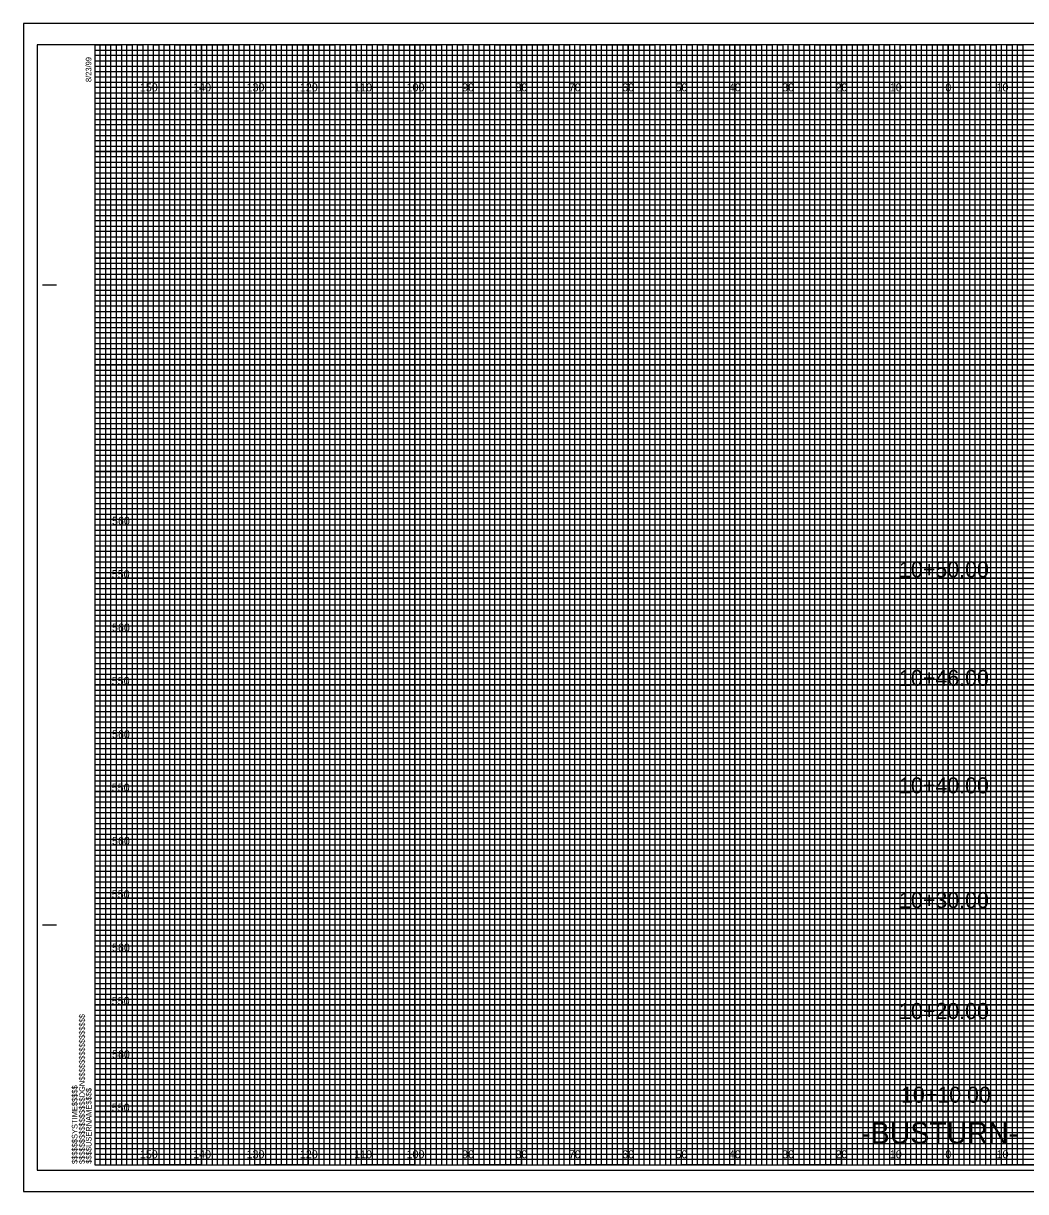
# Model space of a CAD drawing. Extents: x -13 to 323, y -5 to 214.
# Drawn here: x -13.4 to 174.5, y -5 to 214 of the extents above; entities that cross this region are included whole.
import ezdxf

# ---------------------------------------------------------------- set-up
doc = ezdxf.new("R2010")
doc.units = 0
for name, color, linetype in [('Exist Cross Section Cell', 7, 'Continuous'), ('Exist XS Center Line Elevation Label', 7, 'Continuous'), ('Exist XS Ground Line', 7, 'Continuous'), ('Prop XS Alignment Label', 7, 'Continuous'), ('Prop XS DDE Elevations', 7, 'Continuous'), ('Prop XS Ditch Slope Text', 7, 'Continuous'), ('Prop XS Ditch Standard Text', 7, 'Continuous'), ('Prop XS EOT Tick Mark', 7, 'Continuous'), ('Prop XS Finish Grade', 7, 'Continuous'), ('Prop XS Finish Grade Earthwork', 7, 'Continuous'), ('Prop XS Finish Grade Pavement', 7, 'Continuous'), ('Prop XS Label Text', 7, 'Continuous'), ('Prop XS Pvmt Edge Slope', 7, 'Continuous')]:
    doc.layers.add(name, color=color, linetype=linetype)

msp = doc.modelspace()

# ---------------------------------------------------------------- linework, layer by layer
at = {"layer": 'Exist XS Center Line Elevation Label'}
for points in [[(0, 210), (5, 210), (5, 0), (15, 0), (15, 210), (25, 210), (25, 0), (35, 0), (35, 210), (45, 210), (45, 0), (55, 0), (55, 210), (65, 210), (65, 0), (75, 0), (75, 210), (85, 210), (85, 0), (95, 0), (95, 210), (105, 210), (105, 0), (115, 0), (115, 210), (125, 210), (125, 0), (135, 0), (135, 210), (145, 210), (145, 0), (155, 0), (155, 210), (165, 210), (165, 0), (175, 0)], [(0, 205), (275, 205)], [(0, 185), (320, 185), (320, 195), (0, 195)], [(0, 165), (320, 165), (320, 175), (0, 175)], [(0, 145), (320, 145), (320, 155), (0, 155)], [(0, 125), (320, 125), (320, 135), (0, 135)], [(0, 105), (320, 105), (320, 115), (0, 115)], [(0, 85), (320, 85), (320, 95), (0, 95)], [(0, 65), (320, 65), (320, 75), (0, 75)], [(0, 45), (320, 45), (320, 55), (0, 55)], [(0, 25), (320, 25), (320, 35), (0, 35)], [(0, 5), (320, 5), (320, 15), (0, 15)]]:
    msp.add_lwpolyline(points, dxfattribs=at)
at = {"layer": 'Exist XS Ground Line'}
for p, q in [((10, 210), (0, 210)), ((10, 0), (10, 210)), ((30, 210), (20, 210)), ((20, 210), (20, 0)), ((30, 0), (30, 210)), ((50, 210), (40, 210)), ((40, 210), (40, 0)), ((50, 0), (50, 210)), ((70, 210), (60, 210)), ((60, 210), (60, 0)), ((70, 0), (70, 210)), ((90, 210), (80, 210)), ((80, 210), (80, 0)), ((90, 0), (90, 210)), ((110, 210), (100, 210)), ((100, 210), (100, 0)), ((110, 0), (110, 210)), ((130, 210), (120, 210)), ((120, 210), (120, 0)), ((130, 0), (130, 210)), ((150, 210), (140, 210)), ((140, 210), (140, 0)), ((150, 0), (150, 210)), ((170, 210), (160, 210)), ((160, 210), (160, 0)), ((170, 0), (170, 210)), ((20, 0), (10, 0)), ((40, 0), (30, 0)), ((60, 0), (50, 0)), ((80, 0), (70, 0)), ((100, 0), (90, 0)), ((120, 0), (110, 0)), ((140, 0), (130, 0)), ((160, 0), (150, 0)), ((180, 0), (170, 0))]:
    msp.add_line(p, q, dxfattribs=at)
for points in [[(0, 200), (320, 200), (320, 190), (0, 190)], [(0, 180), (320, 180), (320, 170), (0, 170)], [(0, 160), (320, 160), (320, 150), (0, 150)], [(0, 140), (320, 140), (320, 130), (0, 130)], [(0, 120), (320, 120), (320, 110), (0, 110)], [(0, 100), (320, 100), (320, 90), (0, 90)], [(0, 80), (320, 80), (320, 70), (0, 70)], [(0, 60), (320, 60), (320, 50), (0, 50)], [(0, 40), (320, 40), (320, 30), (0, 30)], [(0, 20), (320, 20), (320, 10), (0, 10)]]:
    msp.add_lwpolyline(points, dxfattribs=at)
at = {"layer": 'Prop XS Ditch Slope Text'}
for p, q in [((10, 0), (10, 210)), ((20, 0), (20, 210)), ((30, 0), (30, 210)), ((40, 0), (40, 210)), ((50, 0), (50, 210)), ((60, 0), (60, 210)), ((70, 0), (70, 210)), ((80, 0), (80, 210)), ((90, 0), (90, 210)), ((100, 0), (100, 210)), ((110, 0), (110, 210)), ((120, 0), (120, 210)), ((130, 0), (130, 210)), ((140, 0), (140, 210)), ((150, 0), (150, 210)), ((160, 0), (160, 210)), ((170, 0), (170, 210)), ((0, 200), (320, 200)), ((0, 190), (320, 190)), ((0, 180), (320, 180)), ((0, 170), (320, 170)), ((0, 160), (320, 160)), ((0, 150), (320, 150)), ((0, 140), (320, 140)), ((0, 130), (320, 130)), ((0, 120), (320, 120)), ((0, 110), (320, 110)), ((0, 100), (320, 100)), ((0, 90), (320, 90)), ((0, 80), (320, 80)), ((0, 70), (320, 70)), ((0, 60), (320, 60)), ((0, 50), (320, 50)), ((0, 40), (320, 40)), ((0, 30), (320, 30)), ((0, 20), (320, 20)), ((0, 10), (320, 10))]:
    msp.add_line(p, q, dxfattribs=at)
at = {"layer": 'Prop XS Ditch Standard Text'}
for p, q in [((323.3, 214), (-13.4, 214)), ((-13.4, 214), (-13.4, -5)), ((-13.4, -5), (323.3, -5))]:
    msp.add_line(p, q, dxfattribs=at)
at = {"layer": 'Prop XS EOT Tick Mark'}
msp.add_lwpolyline([(-10.8, -1), (322.4, -1), (322.4, 210), (-10.8, 210)], close=True, dxfattribs=at)
at = {"layer": 'Prop XS Finish Grade'}
for p, q in [((-9.8, 165), (-7.3, 165)), ((-9.7, 165), (-7.2, 165)), ((-9.8, 45), (-7.3, 45)), ((-9.7, 45), (-7.2, 45)), ((0, 0), (0, 0)), ((0, 0), (0, 0)), ((0, 0), (0, 0)), ((0, 0), (0, 0)), ((0, 0), (0, 0)), ((0, 0), (0, 0)), ((0, 0), (0, 0))]:
    msp.add_line(p, q, dxfattribs=at)
msp.add_lwpolyline([(320, 210), (0, 210), (0, 0), (320, 0)], close=True, dxfattribs=at)
at = {"layer": 'Prop XS Finish Grade Earthwork'}
msp.add_lwpolyline([(-13.4, -5), (323.3, -5), (323.3, 214), (-13.4, 214)], close=True, dxfattribs=at)
at = {"layer": 'Prop XS Finish Grade Pavement'}
for p, q in [((0, 209), (260, 209)), ((260, 207.98), (0, 207.98)), ((0, 207.98), (0, 207)), ((0, 207), (260, 207)), ((260, 205.89), (0, 205.89)), ((0, 205.89), (0, 204)), ((0, 204), (320, 204))]:
    msp.add_line(p, q, dxfattribs=at)
for points in [[(0, 203), (270, 203), (320, 203), (320, 202), (0, 202)], [(0, 201), (320, 201), (320, 199), (0, 199)], [(0, 198), (320, 198), (320, 197), (0, 196.98)], [(0, 196), (320, 196), (320, 194), (0, 194)], [(0, 193), (320, 193), (320, 192), (0, 192)], [(0, 191), (320, 191), (320, 189), (0, 189)], [(0, 188), (320, 188), (320, 187), (0, 187)], [(0, 186), (320, 186), (320, 184), (0, 184)], [(0, 183), (320, 183), (320, 182), (0, 182)], [(0, 181), (320, 181), (320, 179), (0, 179)], [(0, 178), (320, 178), (320, 177), (0, 177)], [(0, 176), (320, 176), (320, 173.95), (320, 173), (320, 172), (0, 172)], [(0, 174), (320, 174), (320, 173), (0, 173)], [(0, 171), (320, 171), (320, 169), (0, 169.03)], [(0, 169.03), (320, 169), (320, 168), (0, 168)], [(0, 167), (320, 167), (320, 166), (0, 166)], [(0, 164), (320, 164), (320, 163), (0, 163)], [(0, 162), (320, 162), (320, 161), (0, 161)], [(-0.07, 158.89), (320, 158.89), (320, 157.88), (-0.07, 157.88)], [(0, 157), (320, 157), (320, 156), (0, 156)], [(0, 154), (320, 154), (320, 153), (0, 153)], [(0, 152), (320, 152), (320, 151), (0, 151)], [(0, 149), (320, 149), (320, 148), (0, 148)], [(0, 147), (320, 147), (320, 146), (0, 146)], [(0, 144), (320, 144), (320, 143), (0, 143)], [(0, 142), (320, 142), (320, 141), (0, 141)], [(0, 139), (320, 139), (319.99, 137.98), (0, 138)], [(0, 137), (320, 137), (320, 136), (0, 136)], [(0, 134), (320, 134), (320, 133), (0, 133)], [(0, 132), (320, 132), (320, 131), (0, 131)], [(0, 129), (320, 129), (320, 128), (0, 128)], [(0, 127), (320, 127), (320, 126), (0, 126)], [(0, 124), (320, 124), (320, 123), (0, 123)], [(0, 122), (320, 122), (320, 121), (0, 121)], [(0, 119), (320, 119), (320, 118), (0, 118)], [(0, 116.99), (320.07, 116.91), (320, 116), (0, 116)], [(0, 114), (320, 114), (320, 113), (0, 113)], [(0, 112), (320, 112), (320, 111), (0, 111)], [(0, 109), (320, 109), (320, 108), (0, 108)], [(0, 107), (320, 107), (320, 106), (0, 106)], [(0, 104), (320, 104), (320, 103), (0, 103)], [(0, 102), (320, 102), (320, 101), (0, 101)], [(0, 99), (320, 99), (320, 98), (0, 98)], [(0, 97), (320, 97), (320, 96), (0, 96)], [(0, 94), (320, 94), (320, 93), (0, 93)], [(0, 92), (320, 92), (320, 91), (0, 91)], [(0, 89), (320, 89), (320, 88), (0, 88)], [(0, 87), (320, 87), (320, 86), (0, 86)], [(0, 84), (320, 84), (320, 83), (0, 83)], [(0, 82), (320, 82), (320, 81), (0, 81)], [(0, 79), (320, 79), (319.99, 77.98), (0, 78)], [(0, 77), (320, 77), (320, 76), (0, 76)], [(0, 74), (320, 74), (320, 73), (0, 73)], [(0, 72), (320, 72), (320, 71), (0, 71)], [(0, 69), (320, 69), (320, 68), (0, 68)], [(0, 67), (320, 67), (320, 66), (0, 66)], [(0, 64), (320, 64), (320, 63), (0, 63)], [(0, 62), (320, 62), (320, 61), (0, 61)], [(0, 59), (320, 59), (320, 58), (0, 58)], [(0, 56.99), (320.07, 56.91), (320, 56), (0, 56)], [(0, 54), (320, 54), (320, 53), (0, 53)], [(0, 52), (320, 52), (320, 51), (0, 51)], [(0, 49), (320, 49), (320, 48), (0, 48)], [(0, 47), (320, 47), (320, 46), (0, 46)], [(0, 44), (320, 44), (320, 43), (0, 43)], [(0, 42), (320, 42), (320, 41), (0, 41)], [(0, 39), (320, 39), (320, 38), (0, 38)], [(0, 37), (320, 37), (320, 36), (0, 36)], [(0, 34), (320, 34), (320, 33), (0, 33)], [(0, 32), (320, 32), (320, 31), (0, 31)], [(0, 29), (320, 29), (320, 28), (0, 28)], [(0, 27), (320, 27), (320, 26), (0, 26)], [(0, 24), (320, 24), (320, 23), (0, 23)], [(0, 22), (320, 22), (320, 21), (0, 21)], [(0, 19), (320, 19), (320, 18), (0, 18)], [(0, 17), (320, 17), (320, 16), (0, 16)], [(0, 14), (320, 14), (320, 13), (0, 13)], [(0, 12), (320, 12), (320, 11), (0, 11)], [(0, 9), (320, 9), (320, 8), (0, 8)], [(0, 7), (320, 7), (320, 6), (0, 6)], [(0, 4), (320, 4), (320, 3), (0, 3)], [(0, 2), (320, 2), (320, 1), (0, 1)]]:
    msp.add_lwpolyline(points, dxfattribs=at)
at = {"layer": 'Prop XS Pvmt Edge Slope'}
for points in [[(0, 0), (1, 0), (1, 210), (2, 210), (2, 0)], [(2, 0), (3, 0), (3, 210), (4, 210), (4, 0)], [(5, 0), (6, 0), (6, 210), (7, 210), (7, 0)], [(7, 0), (8, 0), (8, 210), (9, 210), (9, 0)], [(10, 0), (11, 0), (11, 210), (12, 210), (12, 0)], [(12, 0), (13, 0), (13, 210), (14, 210), (14, 0)], [(15, 0), (16, 0), (16, 210), (17, 210), (17, 0)], [(17, 0), (18, 0), (18, 210), (19, 210), (19, 0)], [(20, 0), (21, 0), (21, 210), (22, 210), (22, 0)], [(22, 0), (23, 0), (23, 210), (24, 210), (24, 0)], [(25, 0), (26, 0), (26, 210), (27, 210), (27, 0)], [(27, 0), (28, 0), (28, 210), (29, 210), (29, 0)], [(30, 0), (31, 0), (31, 210), (32, 210), (32, 0)], [(32, 0), (33, 0), (33, 210), (34, 210), (34, 0)], [(35, 0), (36, 0), (36, 210), (37, 210), (37, 0)], [(37, 0), (38, 0), (38, 210), (39, 210), (39, 0)], [(40, 0), (41, 0), (41, 210), (42, 210), (42, 0)], [(42, 0), (43, 0), (43, 210), (44, 210), (44, 0)], [(45, 0), (46, 0), (46, 210), (47, 210), (47, 0)], [(47, 0), (48, 0), (48, 210), (49, 210), (49, 0)], [(50, 0), (51, 0), (51, 210), (52, 210), (52, 0)], [(52, 0), (53, 0), (53, 210), (54, 210), (54, 0)], [(55, 0), (56, 0), (56, 210), (57, 210), (57, 0)], [(57, 0), (58, 0), (58, 210), (59, 210), (59, 0)], [(60, 0), (61, 0), (61, 210), (62, 210), (62, 0)], [(62, 0), (63, 0), (63, 210), (64, 210), (64, 0)], [(65, 0), (66, 0), (66, 210), (67, 210), (67, 0)], [(67, 0), (68, 0), (68, 210), (69, 210), (69, 0)], [(70, 0), (71, 0), (71, 210), (72, 210), (72, 0)], [(72, 0), (73, 0), (73, 210), (74, 210), (74, 0)], [(75, 0), (76, 0), (76, 210), (77, 210), (77, 0)], [(77, 0), (78, 0), (78, 210), (79, 210), (79, 0)], [(80, 0), (81, 0), (81, 210), (82, 210), (82, 0)], [(82, 0), (83, 0), (83, 210), (84, 210), (84, 0)], [(85, 0), (86, 0), (86, 210), (87, 210), (87, 0)], [(87, 0), (88, 0), (88, 210), (89, 210), (89, 0)], [(90, 0), (91, 0), (91, 210), (92, 210), (92, 0)], [(92, 0), (93, 0), (93, 210), (94, 210), (94, 0)], [(95, 0), (96, 0), (96, 210), (97, 210), (97, 0)], [(97, 0), (98, 0), (98, 210), (99, 210), (99, 0)], [(100, 0), (101, 0), (101, 210), (102, 210), (102, 0)], [(102, 0), (103, 0), (103, 210), (104, 210), (104, 0)], [(105, 0), (106, 0), (106, 210), (107, 210), (107, 0)], [(107, 0), (108, 0), (108, 210), (109, 210), (109, 0)], [(110, 0), (111, 0), (111, 210), (112, 210), (112, 0)], [(112, 0), (113, 0), (113, 210), (114, 210), (114, 0)], [(115, 0), (116, 0), (116, 210), (117, 210), (117, 0)], [(117, 0), (118, 0), (118, 210), (119, 210), (119, 0)], [(120, 0), (121, 0), (121, 210), (122, 210), (122, 0)], [(122, 0), (123, 0), (123, 210), (124, 210), (124, 0)], [(125, 0), (126, 0), (126, 210), (127, 210), (127, 0)], [(127, 0), (128, 0), (128, 210), (129, 210), (129, 0)], [(130, 0), (131, 0), (131, 210), (132, 210), (132, 0)], [(132, 0), (133, 0), (133, 210), (134, 210), (134, 0)], [(135, 0), (136, 0), (136, 210), (137, 210), (137, 0)], [(137, 0), (138, 0), (138, 210), (139, 210), (139, 0)], [(140, 0), (141, 0), (141, 210), (142, 210), (142, 0)], [(142, 0), (143, 0), (143, 210), (144, 210), (144, 0)], [(145, 0), (146, 0), (146, 210), (147, 210), (147, 0)], [(147, 0), (148, 0), (148, 210), (149, 210), (149, 0)], [(150, 0), (151, 0), (151, 210), (152, 210), (152, 0)], [(152, 0), (153, 0), (153, 210), (154, 210), (154, 0)], [(155, 0), (156, 0), (156, 210), (157, 210), (157, 0)], [(157, 0), (158, 0), (158, 210), (159, 210), (159, 0)], [(160, 0), (161, 0), (161, 210), (162, 210), (162, 0)], [(162, 0), (163, 0), (163, 210), (164, 210), (164, 0)], [(165, 0), (166, 0), (166, 210), (167, 210), (167, 0)], [(167, 0), (168, 0), (168, 210), (169, 210), (169, 0)], [(170, 0), (171, 0), (171, 210), (172, 210), (172, 0)], [(172, 0), (173, 0), (173, 210), (174, 210), (174, 0)]]:
    msp.add_lwpolyline(points, dxfattribs=at)

# ---------------------------------------------------------------- texts
at = {"layer": 'Exist Cross Section Cell'}
for s, p in [('150', (8.44, 201.25)), ('140', (18.44, 201.25)), ('130', (28.44, 201.25)), ('120', (38.44, 201.25)), ('110', (48.62, 201.25)), ('100', (58.44, 201.25)), ('90', (68.86, 201.25)), ('80', (78.86, 201.25)), ('70', (88.86, 201.25)), ('60', (98.86, 201.25)), ('50', (108.86, 201.25)), ('40', (118.86, 201.25)), ('30', (128.86, 201.25)), ('20', (138.86, 201.25)), ('10', (149.04, 201.25)), ('0', (159.45, 201.25)), ('0', (159.45, 201.25)), ('10', (169.04, 201.25)), ('150', (8.44, 1.25)), ('140', (18.44, 1.25)), ('130', (28.44, 1.25)), ('120', (38.44, 1.25)), ('110', (48.62, 1.25)), ('100', (58.44, 1.25)), ('90', (68.86, 1.25)), ('80', (78.86, 1.25)), ('70', (88.86, 1.25)), ('60', (98.86, 1.25)), ('50', (108.86, 1.25)), ('40', (118.86, 1.25)), ('30', (128.86, 1.25)), ('20', (138.86, 1.25)), ('10', (149.04, 1.25)), ('0', (159.45, 1.25)), ('0', (159.45, 1.25)), ('10', (169.04, 1.25))]:
    msp.add_text(s, height=1.5, dxfattribs=at).set_placement(p)
at = {"layer": 'Prop XS Alignment Label'}
msp.add_text('-BUSTURN-', height=4, dxfattribs=at).set_placement((143.66, 4))
at = {"layer": 'Prop XS DDE Elevations'}
for s, p in [('560', (3.22, 120)), ('550', (3.17, 110)), ('560', (3.22, 100)), ('550', (3.17, 90)), ('560', (3.22, 80)), ('550', (3.17, 70)), ('560', (3.22, 60)), ('550', (3.17, 50)), ('560', (3.22, 40)), ('550', (3.17, 30)), ('560', (3.22, 20)), ('540', (3.22, 20)), ('550', (3.17, 10))]:
    msp.add_text(s, height=1.5, dxfattribs=at).set_placement(p)
at = {"layer": 'Prop XS Finish Grade'}
for s, p in [('8/23/99', (-0.65, 203)), ('$$$$$$$$$$$$$$$$DGN$$$$$$$$$$$$$$$$', (-1.88, 0.18)), ('$$$$$$SYSTIME$$$$$', (-3.26, 0.18)), ('$$$$USERNAME$$$$', (-0.62, 0.23))]:
    msp.add_text(s, height=1.05, rotation=90, dxfattribs=at).set_placement(p)
at = {"layer": 'Prop XS Label Text'}
for s, p in [('10+50.00', (150.77, 110.15)), ('10+46.00', (150.77, 89.81)), ('10+40.00', (150.77, 69.66)), ('10+30.00', (150.77, 48.16)), ('10+20.00', (150.77, 27.36)), ('10+10.00', (151.13, 11.67))]:
    msp.add_text(s, height=3, dxfattribs=at).set_placement(p)

doc.saveas('drawing.dxf')
